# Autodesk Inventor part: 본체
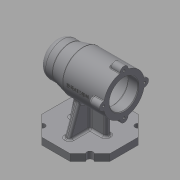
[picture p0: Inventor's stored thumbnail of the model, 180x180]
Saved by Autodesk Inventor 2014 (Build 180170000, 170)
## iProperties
Created: 2021-01
Part Number: 본체
Material: Generic
Document SubType Name: Modeling
Designer: kh
Density: 1 g/cm^3
Appearance: Default
Author: kh
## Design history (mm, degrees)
sketch "Sketch1" dims "d0" = 100
  geometry: L1 (20.711, 50)-(50, 20.711); L2 (50, 20.711)-(50, -20.711); L3 (50, -20.711)-(20.711, -50); L4 (20.711, -50)-(-20.711, -50); L5 (-20.711, -50)-(-50, -20.711); L6 (-50, -20.711)-(-50, 20.711); L7 (-50, 20.711)-(-20.711, 50); L8 (-20.711, 50)-(20.711, 50); L9 (0, 0)-(0, 50); L10 (0, 0)-(35.355, 35.355); C1 r 4.5 at (35.355, 35.355); 2 further points
  constraints: 20 end point, 3 coincident, 2 midpoint, 1 centre point, 1 perpendicular, 1 vertical, 1 vertical alignment, 19 other
  dimensions: "d3" = 9 diameter of C1
extrude "Extrusion1" new body sketch "Sketch1" distance "d1" = 10; taper "d2" = 0 deg
extrude "Extrusion2" cut sketch "Sketch1" distance "d4" = 10; taper "d5" = 0 deg
pattern_circular "Circular Pattern1" dims angle "d7" = 360 deg
sketch "Sketch2"
  geometry: L1 (0, 0)-(0, 75); L2 (50, 75)-(-50, 75); L3 (-50, 0)-(-50, 10) reference; L4 (-50, 75)-(-50, 105); L5 (-50, 105)-(10, 105); L6 (10, 105)-(30, 100); L7 (30, 100)-(50, 100); L8 (50, 100)-(50, 75); L9 (44, 75)-(44, 85.5); L10 (44, 85.5)-(41, 85.5); L11 (41, 85.5)-(41, 91); L12 (41, 91)-(37, 91); L13 (37, 91)-(37, 92.5); L14 (37, 92.5)-(19, 92.5); L15 (19, 92.5)-(19, 96); L16 (19, 96)-(7, 96); L17 (7, 96)-(7, 99); L18 (7, 99)-(-35, 99); L19 (-35, 99)-(-35, 96); L20 (-35, 96)-(-50, 96)
  constraints: 38 end point, 12 parallel, 4 perpendicular, 3 point on line, 1 collinear, 1 midpoint, 1 vertical
  dimensions: "d9" = 75 distance of L1.start L1.end; "d10" = 60 diameter of L5 L2; "d11" = 42 diameter of L20 L2; "d12" = 48 diameter of L18 L2; "d13" = 42 diameter of L16 L2; "d14" = 21 diameter of L10 L2; "d15" = 32 diameter of L12 L2; "d16" = 35 diameter of L14 L2; "d17" = 15 distance of L19.end L20.end; "d18" = 42 distance of L17.end L18.end; "d19" = 12 distance of L15.end L16.end; "d20" = 18 distance of L13.end L14.end; "d21" = 4 distance of L11.end L12.end; "d22" = 3 distance of L9.end L10.end; "d23" = 20 distance of L6.end L7.end; "d24" = 40 distance from line of L5.end L8; "d25" = 100 distance between parallel lines of L4 L8; "d26" = 50 diameter of L7 L2
revolve "Revolution1" sketch "Sketch2" stored, may be unused: angle "d27" = 90 deg
sketch "Sketch3"
  geometry: L1 (-50, 0)-(-50, 10) reference; L2 (50, 0)-(50, 10) reference; L3 (-50, 10)-(-27, 10); L4 (-27, 10)-(-27, 33.653); 1 further point
  constraints: 4 end point, 2 perpendicular
  dimensions: "d28" = 23 distance of L1.end L3.end
feature "Rib1" sketch "Sketch3" dims "d29" = 1, "d30" = 8, "d31" = 0, "d32" = 0, "d33" = 1, "d34" = 1
sketch "Sketch4"
  geometry: L1 (50, 0)-(50, 10) reference; L2 (50, 10)-(27, 10); L3 (27, 10)-(21.689, 37.325); 1 further point
  constraints: 4 end point, 1 perpendicular
  dimensions: "d35" = 23 distance of L1.end L2.end; "d36" = 101 deg angle of L2 L3
feature "Rib2" sketch "Sketch4" dims "d37" = 1, "d38" = 8, "d39" = 0, "d40" = 0, "d41" = 1, "d42" = 1
sketch "Sketch5"
  geometry: L1 (50, 0)-(50, 10) reference; L2 (50, 10)-(35, 10); L3 (35, 10)-(25.997, 34.736); 1 further point
  constraints: 4 end point, 1 perpendicular
  dimensions: "d43" = 15 distance of L1.end L2.end; "d44" = 110 deg angle of L3 L2
feature "Rib3" sketch "Sketch5" dims "d45" = 1, "d46" = 8, "d47" = 0, "d48" = 0, "d49" = 1, "d50" = 1
mirror "Mirror1"
sketch "Sketch6"
  geometry: L1 (0, 0)-(-30, 0); C1 r 6 at (-30, 0); 1 further point
  constraints: 2 end point, 1 centre point, 1 coincident, 1 horizontal, 1 horizontal alignment, 1 other
  dimensions: "d51" = 12 diameter of C1
extrude "Extrusion3" join sketch "Sketch6" distance "d52" = 16; taper "d53" = 0 deg
hole "Hole1" diameter "d56" = 3.242; stored, may be unused: countersink angle "d60" = 90 deg, drill point angle "d62" = 118 deg; dims "d54" = 10, "d55" = 10, "d57" = 8, "d58" = 4, "d59" = 2, "d61" = 10
pattern_circular "Circular Pattern2" dims angle "d64" = 360 deg
workplane "Work Plane1"
sketch "Sketch7"
  geometry: L1 (-31.795, 14.063)-(15.795, 14.063); L2 (15.795, 14.063)-(15.795, -13.795); L3 (15.795, -13.795)-(-31.795, -13.795); L4 (-31.795, -13.795)-(-31.795, 14.063); L5 (15.795, -13.795)-(-31.795, 14.063); L6 (-30, 30)-(-30, -29.732) reference; L7 (-30, 0.134)-(32.392, 0.134); L8 (30, 29.4)-(30, 5.97) reference; 2 further points
  constraints: 4 end point, 2 midpoint, 1 perpendicular, 1 point on line, 2 other
  dimensions: "d66" = 38 distance from line of L8 point (-8, 0.134)
emboss "Emboss1" sketch "Sketch7" dims "d9" = 75, "d67" = 0.5, "d68" = 0
fillet "Fillet1" dims "d69" = 0.3, "d70" = 3
fillet "Fillet2" dims "d71" = 3
fillet "Fillet3" dims "d72" = 1
fillet "Fillet4" dims "d73" = 10, "d74" = 3
fillet "Fillet5" dims "d75" = 3
chamfer "Chamfer1" distance "d76" = 1; stored, may be unused: second distance "d77" = 2, angle "d78" = 45 deg
body "Solid1"
